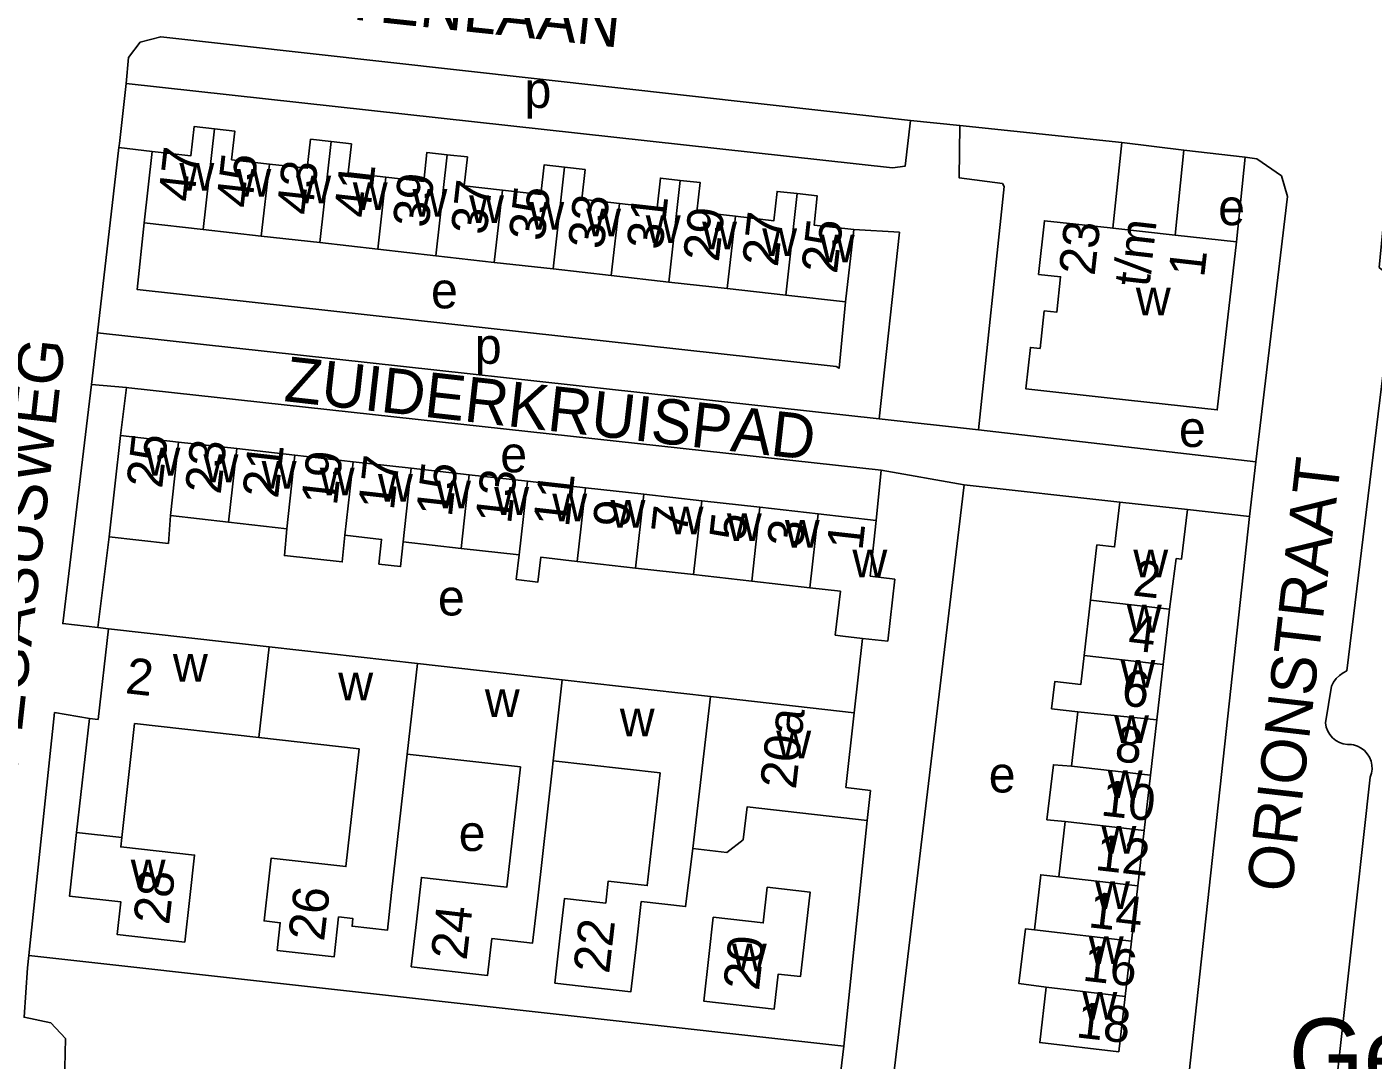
# Model space of a CAD drawing. Extents: x 161936 to 163647, y 386450 to 388633.
# Drawn here: x 162379.9 to 162529.2, y 386841.4 to 386956 of the extents above; entities that cross this region are included whole.
import ezdxf

# ---------------------------------------------------------------- set-up
doc = ezdxf.new("R2010")
doc.units = 0
for name, color, linetype in [('BLT_Basislijn', 7, 'Continuous'), ('BLT_Bebouwing', 7, 'Continuous'), ('BLT_Bebouwing_beschrifting', 7, 'Continuous'), ('BLT_Centroide', 7, 'Continuous'), ('BLT_Huisnummer', 7, 'Continuous'), ('BLT_Huisnummer_ tussenligend', 7, 'Continuous'), ('BLT_Huisnummer_reeks', 7, 'Continuous'), ('BLT_Onderverdeling_panden', 7, 'Continuous'), ('BLT_Straatnaam', 7, 'Continuous')]:
    doc.layers.add(name, color=color, linetype=linetype)

msp = doc.modelspace()

# ---------------------------------------------------------------- linework, layer by layer
at = {"layer": 'BLT_Basislijn'}
for p, q in [((162477.88, 386945.61), (162483.35, 386945.05)), ((162483.35, 386945.05), (162501.3, 386943.14)), ((162387.76, 386922.04), (162390.12, 386942.6)), ((162393.82, 386942.16), (162390.12, 386942.6)), ((162501.3, 386943.14), (162500.32, 386933.65)), ((162501.3, 386943.14), (162508.18, 386942.32)), ((162507.21, 386932.89), (162508.18, 386942.32)), ((162514.98, 386941.51), (162508.18, 386942.32)), ((162514.98, 386941.51), (162514.01, 386932.13)), ((162387.07, 386916.31), (162387.76, 386922.04)), ((162387.76, 386922.04), (162474.42, 386912.5)), ((162390.95, 386915.99), (162387.07, 386916.31)), ((162390.95, 386915.99), (162390.3, 386910.64)), ((162485.43, 386911.3), (162474.42, 386912.5)), ((162485.43, 386911.3), (162516.16, 386907.74)), ((162474.08, 386901.25), (162474.62, 386906.8)), ((162474.62, 386906.8), (162483.81, 386905.2)), ((162516.16, 386907.74), (162515.46, 386901.67)), ((162475.82, 386838.03), (162483.81, 386905.2)), ((162483.81, 386905.2), (162501.08, 386903.28)), ((162508.58, 386902.44), (162515.46, 386901.67)), ((162389.04, 386899.42), (162387.79, 386889.36)), ((162387.79, 386889.36), (162388.95, 386889.23)), ((162471.65, 386879.91), (162472.54, 386888.16)), ((162524.56, 386882.86), (162523.88, 386878.78)), ((162380.14, 386853), (162382.97, 386879.94)), ((162382.97, 386879.94), (162386.86, 386879.29)), ((162470.47, 386842.93), (162473.08, 386867.96)), ((162379.97, 386851.64), (162380.14, 386853)), ((162380.14, 386853), (162470.47, 386842.93)), ((162469.63, 386835.62), (162470.47, 386842.93))]:
    msp.add_line(p, q, dxfattribs=at)
for points in [[(162390.94, 386949.68), (162391.2, 386952.59), (162392.47, 386954.27), (162394.76, 386954.88), (162477.88, 386945.61)], [(162390.12, 386942.6), (162390.17, 386943.04), (162390.94, 386949.68)], [(162390.94, 386949.68), (162475.9, 386940.33), (162477.27, 386940.52), (162477.88, 386945.61)], [(162483.35, 386945.05), (162483.26, 386939.24), (162488.07, 386938.61), (162488.28, 386938.26), (162485.43, 386911.3)], [(162514.98, 386941.51), (162516.28, 386941.34), (162518.99, 386939.44), (162519.66, 386937.17), (162516.16, 386907.74)], [(162392.93, 386934.24), (162392.13, 386926.86), (162469.63, 386918.3), (162469.96, 386918.11), (162470.69, 386925.47)], [(162471.6, 386933.5), (162476.65, 386933.2), (162474.42, 386912.5)], [(162526.26, 386884.56), (162531.53, 386927.94), (162529.83, 386929.3), (162530.3, 386934.24)], [(162387.07, 386916.31), (162383.9, 386889.8), (162387.79, 386889.36)], [(162474.62, 386906.8), (162391.22, 386915.96), (162390.95, 386915.99)], [(162515.46, 386901.67), (162507.38, 386827.08), (162506.26, 386825.43), (162503.72, 386825.09), (162503.24, 386825.2), (162501.96, 386826.44), (162502.42, 386835.57), (162486.92, 386836.72)], [(162524.56, 386882.86), (162524.79, 386883.31), (162525.08, 386883.71), (162525.44, 386884.06), (162525.85, 386884.35), (162526.26, 386884.56)], [(162526.77, 386876.4), (162526.31, 386876.39), (162525.86, 386876.47), (162525.42, 386876.62), (162525.02, 386876.85), (162524.67, 386877.14), (162524.37, 386877.49), (162524.13, 386877.88), (162523.97, 386878.31), (162523.88, 386878.78)], [(162528.83, 386872.77), (162528.97, 386873.2), (162529.04, 386873.66), (162529.02, 386874.11), (162528.93, 386874.56), (162528.75, 386874.99), (162528.51, 386875.37), (162528.21, 386875.72), (162527.84, 386876), (162527.44, 386876.21), (162527, 386876.35), (162526.77, 386876.4)], [(162477.84, 386821.19), (162508.49, 386817.72), (162511.93, 386818.04), (162515.56, 386820.08), (162517.72, 386822.78), (162518.68, 386825.55), (162518.96, 386830.28), (162519.77, 386831.61), (162520.17, 386831.95), (162524.31, 386831.95), (162528.83, 386872.77)], [(162379.97, 386851.64), (162379.61, 386846.15), (162382.58, 386845.51), (162384.19, 386843.79), (162384.1, 386838.92), (162458.9, 386830.4)]]:
    msp.add_lwpolyline(points, dxfattribs=at)
at = {"layer": 'BLT_Bebouwing'}
for p, q in [((162392.93, 386934.24), (162393.82, 386942.16)), ((162399.47, 386933.51), (162392.93, 386934.24)), ((162405.91, 386932.78), (162399.47, 386933.51)), ((162471.6, 386933.5), (162470.69, 386925.47)), ((162500.32, 386933.65), (162507.21, 386932.89)), ((162412.38, 386932.05), (162405.91, 386932.78)), ((162418.82, 386931.32), (162412.38, 386932.05)), ((162507.21, 386932.89), (162514.01, 386932.13)), ((162425.25, 386930.6), (162418.82, 386931.32)), ((162431.74, 386929.86), (162425.25, 386930.6)), ((162438.25, 386929.13), (162431.74, 386929.86)), ((162444.71, 386928.4), (162438.25, 386929.13)), ((162451.09, 386927.68), (162444.71, 386928.4)), ((162457.56, 386926.95), (162451.09, 386927.68)), ((162464.05, 386926.22), (162457.56, 386926.95)), ((162470.69, 386925.47), (162464.05, 386926.22)), ((162390.3, 386910.64), (162389.04, 386899.42)), ((162396.74, 386909.92), (162390.3, 386910.64)), ((162403.19, 386909.2), (162396.74, 386909.92)), ((162409.63, 386908.48), (162403.19, 386909.2)), ((162416.08, 386907.75), (162409.63, 386908.48)), ((162422.52, 386907.03), (162416.08, 386907.75)), ((162428.97, 386906.31), (162422.52, 386907.03)), ((162435.41, 386905.59), (162428.97, 386906.31)), ((162441.86, 386904.86), (162435.41, 386905.59)), ((162448.3, 386904.14), (162441.86, 386904.86)), ((162454.75, 386903.42), (162448.3, 386904.14)), ((162461.19, 386902.7), (162454.75, 386903.42)), ((162467.64, 386901.97), (162461.19, 386902.7)), ((162508.58, 386902.44), (162501.08, 386903.28)), ((162395.62, 386898.68), (162395.83, 386901.77)), ((162395.83, 386901.77), (162402.27, 386901.05)), ((162402.27, 386901.05), (162408.72, 386900.32)), ((162474.08, 386901.25), (162467.64, 386901.97)), ((162473.39, 386895.06), (162474.08, 386901.25)), ((162389.04, 386899.42), (162395.62, 386898.68)), ((162421.65, 386898.86), (162428.05, 386898.14)), ((162428.05, 386898.14), (162434.5, 386897.41)), ((162440.94, 386896.69), (162447.39, 386895.96)), ((162447.39, 386895.96), (162453.83, 386895.23)), ((162453.83, 386895.23), (162460.27, 386894.51)), ((162476.14, 386894.74), (162473.39, 386895.06)), ((162475.35, 386887.84), (162476.14, 386894.74)), ((162460.27, 386894.51), (162466.72, 386893.78)), ((162466.72, 386893.78), (162470.1, 386893.4)), ((162469.54, 386888.5), (162470.1, 386893.4)), ((162497.84, 386892.39), (162497.14, 386886.26)), ((162506.6, 386891.39), (162505.9, 386885.25)), ((162387.82, 386879.18), (162388.95, 386889.23)), ((162388.95, 386889.23), (162406.78, 386887.22)), ((162406.78, 386887.22), (162423.23, 386885.37)), ((162470.39, 386888.4), (162469.54, 386888.5)), ((162472.54, 386888.16), (162470.39, 386888.4)), ((162475.35, 386887.84), (162472.54, 386888.16)), ((162423.23, 386885.37), (162439.28, 386883.56)), ((162505.9, 386885.25), (162505.19, 386879.12)), ((162439.28, 386883.56), (162455.7, 386881.71)), ((162455.7, 386881.71), (162471.65, 386879.91)), ((162471.65, 386879.91), (162470.71, 386871.61)), ((162496.42, 386880.02), (162495.72, 386873.99)), ((162386.86, 386879.29), (162387.82, 386879.18)), ((162405.65, 386877.17), (162391.86, 386878.72)), ((162505.19, 386879.12), (162504.49, 386872.99)), ((162416.75, 386875.92), (162405.65, 386877.17)), ((162422.09, 386875.32), (162434.64, 386873.9)), ((162438.26, 386874.58), (162438.15, 386873.53)), ((162450.13, 386873.24), (162438.26, 386874.58)), ((162504.49, 386872.99), (162503.78, 386866.85)), ((162470.71, 386871.61), (162473.46, 386871.3)), ((162473.08, 386867.96), (162473.46, 386871.3)), ((162495.02, 386867.86), (162494.31, 386861.73)), ((162503.78, 386866.85), (162503.08, 386860.72)), ((162503.08, 386860.72), (162502.37, 386854.59)), ((162502.37, 386854.59), (162501.67, 386848.45))]:
    msp.add_line(p, q, dxfattribs=at)
for points in [[(162393.82, 386942.16), (162398.11, 386941.68), (162398.48, 386944.93), (162400.73, 386944.67)], [(162400.73, 386944.67), (162402.97, 386944.42), (162402.61, 386941.24), (162406.81, 386940.76)], [(162406.81, 386940.76), (162411.01, 386940.29), (162411.37, 386943.51), (162413.64, 386943.25)], [(162413.64, 386943.25), (162415.9, 386943), (162415.54, 386939.77), (162419.72, 386939.3)], [(162419.72, 386939.3), (162423.91, 386938.82), (162424.27, 386942.06), (162426.52, 386941.8)], [(162426.52, 386941.8), (162428.76, 386941.55), (162428.4, 386938.34), (162432.64, 386937.86)], [(162432.64, 386937.86), (162436.88, 386937.38), (162437.25, 386940.66), (162439.52, 386940.4)], [(162439.52, 386940.4), (162441.8, 386940.15), (162441.43, 386936.85), (162445.61, 386936.38)], [(162445.61, 386936.38), (162449.79, 386935.9), (162450.16, 386939.2), (162452.36, 386938.95)], [(162452.36, 386938.95), (162454.57, 386938.71), (162454.2, 386935.45), (162458.46, 386934.97)], [(162458.46, 386934.97), (162462.73, 386934.48), (162463.09, 386937.73), (162465.32, 386937.48)], [(162465.32, 386937.48), (162467.54, 386937.23), (162467.18, 386934), (162471.6, 386933.5)], [(162500.32, 386933.65), (162500, 386933.68), (162492.73, 386934.48), (162492.08, 386928.53), (162494.52, 386928.26), (162494.09, 386924.32), (162492.7, 386924.47), (162492.24, 386920.31), (162491.18, 386920.43), (162490.67, 386915.83), (162500, 386914.8), (162511.89, 386913.49), (162514.01, 386932.13)], [(162501.08, 386903.28), (162500.51, 386898.31), (162498.55, 386898.52), (162497.84, 386892.39)], [(162506.6, 386891.39), (162507.33, 386897), (162507.91, 386896.94), (162508.58, 386902.44)], [(162408.72, 386900.32), (162408.47, 386897.35), (162414.89, 386896.63), (162415.16, 386899.59)], [(162415.16, 386899.59), (162419.25, 386899.13), (162418.94, 386896.4), (162421.34, 386896.13), (162421.65, 386898.86)], [(162434.5, 386897.41), (162434.18, 386894.69), (162436.57, 386894.41), (162436.88, 386897.15), (162440.94, 386896.69)], [(162497.14, 386886.26), (162496.76, 386883.03), (162493.87, 386883.36), (162493.52, 386880.35), (162496.42, 386880.02)], [(162385.43, 386866.64), (162386.86, 386879.29)], [(162391.86, 386878.72), (162390.43, 386866.08)], [(162422.09, 386875.32), (162420.36, 386859.97), (162419.89, 386855.79), (162415.97, 386856.23), (162416.07, 386857.09), (162414.48, 386857.27), (162413.98, 386852.84), (162407.67, 386853.56), (162408.01, 386856.62), (162406.22, 386856.82), (162406.78, 386861.79), (162407.01, 386863.8), (162415.28, 386862.86), (162416.75, 386875.92)], [(162434.64, 386873.9), (162433.14, 386860.58), (162432.1, 386860.69)], [(162495.72, 386873.99), (162493.72, 386874.15), (162493.01, 386868.05), (162495.02, 386867.86)], [(162438.15, 386873.53), (162436.55, 386859.34), (162435.99, 386854.37), (162431.46, 386854.88)], [(162447.45, 386853.94), (162446.88, 386848.97), (162438.46, 386849.93), (162439.02, 386854.9), (162439.53, 386859.32), (162444.09, 386858.8), (162444.37, 386861.24), (162448.7, 386860.75), (162450.13, 386873.24)], [(162473.08, 386867.96), (162459.77, 386869.46), (162459.32, 386865.82), (162457.51, 386864.42), (162453.74, 386864.85)], [(162390.43, 386866.08), (162390.32, 386865.04), (162398.51, 386864.12), (162397.98, 386859.43), (162397.42, 386854.47), (162389.94, 386855.31), (162390.35, 386858.93), (162384.64, 386859.58), (162385.43, 386866.64)], [(162453.74, 386864.85), (162452.95, 386858.42), (162448.02, 386858.98)], [(162494.31, 386861.73), (162492.31, 386861.95), (162491.61, 386855.85)], [(162431.46, 386854.88), (162430.99, 386850.79), (162422.54, 386851.74), (162423.1, 386856.71), (162423.66, 386861.65), (162432.1, 386860.69)], [(162462, 386860.57), (162461.56, 386856.6), (162456.02, 386857.23), (162455.53, 386852.89), (162454.97, 386847.92), (162462.77, 386847.04), (162463.21, 386850.93), (162465.68, 386850.65), (162466.74, 386860.03), (162462, 386860.57)], [(162448.02, 386858.98), (162447.45, 386853.94)], [(162491.61, 386855.85), (162490.61, 386855.94), (162489.9, 386849.87), (162492.9, 386849.46)], [(162492.9, 386849.46), (162492.2, 386843.33), (162500.96, 386842.32), (162501.67, 386848.45)]]:
    msp.add_lwpolyline(points, dxfattribs=at)
at = {"layer": 'BLT_Onderverdeling_panden'}
for p, q in [((162400.73, 386944.67), (162399.47, 386933.51)), ((162413.64, 386943.25), (162412.38, 386932.05)), ((162426.52, 386941.8), (162425.25, 386930.6)), ((162406.81, 386940.76), (162405.91, 386932.78)), ((162439.52, 386940.4), (162438.25, 386929.13)), ((162419.72, 386939.3), (162418.82, 386931.32)), ((162432.64, 386937.86), (162431.74, 386929.86)), ((162452.36, 386938.95), (162451.09, 386927.68)), ((162445.61, 386936.38), (162444.71, 386928.4)), ((162465.32, 386937.48), (162464.05, 386926.22)), ((162458.46, 386934.97), (162457.56, 386926.95)), ((162396.74, 386909.92), (162395.83, 386901.77)), ((162403.19, 386909.2), (162402.27, 386901.05)), ((162409.63, 386908.48), (162408.72, 386900.32)), ((162416.08, 386907.75), (162415.16, 386899.59)), ((162422.52, 386907.03), (162421.65, 386898.86)), ((162428.97, 386906.31), (162428.05, 386898.14)), ((162435.41, 386905.59), (162434.5, 386897.41)), ((162441.86, 386904.86), (162440.94, 386896.69)), ((162448.3, 386904.14), (162447.39, 386895.96)), ((162454.75, 386903.42), (162453.83, 386895.23)), ((162461.19, 386902.7), (162460.27, 386894.51)), ((162467.64, 386901.97), (162466.72, 386893.78)), ((162506.6, 386891.39), (162497.84, 386892.39)), ((162405.65, 386877.17), (162406.78, 386887.22)), ((162505.9, 386885.25), (162497.14, 386886.26)), ((162422.09, 386875.32), (162423.23, 386885.37)), ((162438.26, 386874.58), (162439.28, 386883.56)), ((162453.74, 386864.85), (162455.7, 386881.71)), ((162505.19, 386879.12), (162496.42, 386880.02)), ((162504.49, 386872.99), (162495.72, 386873.99)), ((162503.78, 386866.85), (162495.02, 386867.86)), ((162390.43, 386866.08), (162385.43, 386866.64)), ((162503.08, 386860.72), (162494.31, 386861.73)), ((162502.37, 386854.59), (162491.61, 386855.85)), ((162501.67, 386848.45), (162492.9, 386849.46))]:
    msp.add_line(p, q, dxfattribs=at)

# ---------------------------------------------------------------- texts
at = {"layer": 'BLT_Bebouwing_beschrifting'}
msp.add_text('Gezondheidscentrum', height=8, dxfattribs=at).set_placement((162519.82, 386838.02))
at = {"layer": 'BLT_Centroide'}
for s, p in [('p', (162435.09, 386946.99)), ('w', (162396.83, 386937.81)), ('w', (162403.14, 386937.14)), ('w', (162409.78, 386936.39)), ('w', (162416.05, 386935.67)), ('w', (162422.67, 386934.92)), ('w', (162428.95, 386934.23)), ('w', (162435.62, 386933.48)), ('e', (162511.99, 386933.98)), ('w', (162441.92, 386932.75)), ('w', (162448.53, 386932)), ('w', (162454.78, 386931.31)), ('w', (162461.44, 386930.56)), ('w', (162467.83, 386929.86)), ('e', (162424.72, 386924.76)), ('w', (162502.86, 386923.97)), ('p', (162429.58, 386918.61)), ('e', (162507.64, 386909.39)), ('e', (162432.4, 386906.58)), ('w', (162393.06, 386906.22)), ('w', (162399.5, 386905.48)), ('w', (162405.95, 386904.75)), ('w', (162412.39, 386904.03)), ('w', (162418.84, 386903.31)), ('w', (162425.28, 386902.58)), ('w', (162431.73, 386901.86)), ('w', (162438.17, 386901.14)), ('w', (162444.62, 386900.42)), ('w', (162451.06, 386899.69)), ('w', (162457.52, 386898.95)), ('w', (162463.95, 386898.23)), ('w', (162471.44, 386894.92)), ('w', (162502.58, 386894.94)), ('e', (162425.49, 386890.7)), ('w', (162501.86, 386888.81)), ('w', (162396.11, 386883.34)), ('w', (162501.16, 386882.69)), ('w', (162414.44, 386881.27)), ('w', (162430.69, 386879.44)), ('w', (162445.65, 386877.31)), ('w', (162500.45, 386876.56)), ('w', (162463, 386874.84)), ('e', (162486.55, 386871.07)), ('w', (162499.75, 386870.44)), ('e', (162427.79, 386864.58)), ('w', (162499.05, 386864.28)), ('w', (162391.43, 386860.56)), ('w', (162498.34, 386858.16)), ('w', (162458.08, 386851.24)), ('w', (162497.64, 386852.03)), ('w', (162496.94, 386845.88))]:
    msp.add_text(s, height=4, dxfattribs=at).set_placement(p)
at = {"layer": 'BLT_Huisnummer'}
for s, rotation, p in [('47', 83.568, (162398.43, 386936.47)), ('41', 83.5684, (162417.91, 386934.69)), ('37', 83.5702, (162430.87, 386932.82)), ('33', 83.566, (162443.85, 386931.23)), ('29', 83.5696, (162456.62, 386929.82)), ('25', 83.5635, (162469.73, 386928.51)), ('25', 83.6027, (162394.91, 386904.7)), ('21', 83.6012, (162407.76, 386903.59)), ('17', 83.6075, (162420.6, 386902.28)), ('13', 83.606, (162433.59, 386900.77)), ('9', 83.6045, (162446.61, 386900.32)), ('5', 83.603, (162459.52, 386898.88)), ('1', 83.607, (162472.54, 386897.82)), ('2', 353.4518, (162502.42, 386892.93)), ('2', 353.5732, (162390.74, 386882.09)), ('6', 353.4461, (162501.17, 386880.75)), ('20a', 83.5704, (162465.16, 386871.34)), ('10', 353.4461, (162498.87, 386868.54)), ('28', 83.57, (162395.68, 386856.31)), ('26', 83.568, (162412.86, 386854.48)), ('14', 353.4468, (162497.49, 386856.14)), ('24', 83.5568, (162428.66, 386852.38)), ('22', 83.489, (162444.46, 386850.89)), ('20', 83.5626, (162461.07, 386849.01)), ('18', 353.4404, (162496.13, 386843.93))]:
    msp.add_text(s, height=4, rotation=rotation, dxfattribs=at).set_placement(p)
at = {"layer": 'BLT_Huisnummer_ tussenligend'}
for s, rotation, p in [('45', 83.5684, (162404.85, 386935.79)), ('43', 83.5684, (162411.55, 386935.01)), ('39', 83.5702, (162424.43, 386933.61)), ('35', 83.566, (162437.29, 386932.14)), ('31', 83.5696, (162450.36, 386931.17)), ('27', 83.5635, (162463.16, 386929.27)), ('23', 83.6012, (162401.4, 386904.05)), ('19', 83.6075, (162414.29, 386902.8)), ('15', 83.606, (162427.02, 386901.54)), ('11', 83.6045, (162440.01, 386900.41)), ('7', 83.603, (162453.08, 386899.64)), ('3', 83.607, (162465.92, 386898.15)), ('4', 353.4518, (162501.89, 386886.88)), ('8', 353.4461, (162500.4, 386874.56)), ('12', 353.4461, (162498.24, 386862.49)), ('16', 353.4468, (162496.85, 386850.22))]:
    msp.add_text(s, height=4, rotation=rotation, dxfattribs=at).set_placement(p)
at = {"layer": 'BLT_Huisnummer_reeks'}
for s, rotation, p in [('23', 83.6967, (162498.28, 386928.3)), ('t/m', 83.4926, (162504.34, 386927.05)), ('1', 83.4926, (162510.43, 386928.11))]:
    msp.add_text(s, height=4, rotation=rotation, dxfattribs=at).set_placement(p)
at = {"layer": 'BLT_Straatnaam'}
for s, height, rotation, p in [('PLANETENLAAN', 5, 353.9595, (162393.03, 386959.23)), ('PEGASUSWEG', 5, 83.6654, (162378.84, 386873.14)), ('ZUIDERKRUISPAD', 4.9999, 353.6138, (162408.33, 386914.48)), ('ORIONSTRAAT', 5, 83.4326, (162520.1, 386859.88))]:
    msp.add_text(s, height=height, rotation=rotation, dxfattribs=at).set_placement(p)

doc.saveas('drawing.dxf')
